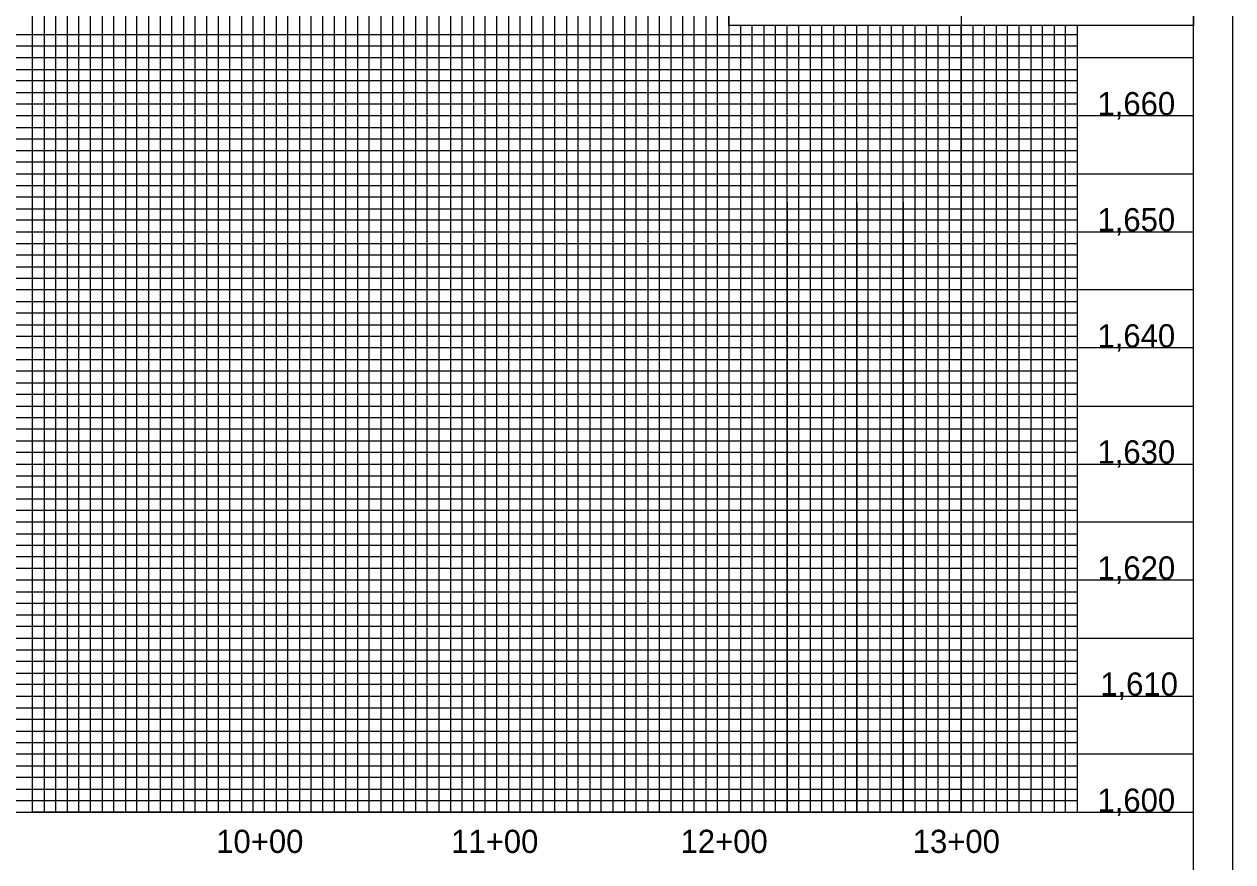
# Model space of a CAD drawing. Extents: x 505602 to 507286, y 483109 to 484209.
# Drawn here: x 506765 to 507286, y 483662 to 484023 of the extents above; entities that cross this region are included whole.
import ezdxf

# ---------------------------------------------------------------- set-up
doc = ezdxf.new("R2010")
doc.units = 0
for name, color, linetype in [('Exist Vertical Profile Vertical Axis Label', 7, 'Continuous'), ('Sheet Layout Profile Border Port 2', 7, 'Continuous'), ('Sheet Plot Border Outside CELL', 7, 'Continuous'), ('Sheet Profile CELL', 7, 'Continuous'), ('Sheet Profile Grid Major CELL', 7, 'Continuous'), ('Sheet Profile Grid Middle CELL', 7, 'Continuous'), ('Sheet Profile Grid Minor CELL', 7, 'Continuous'), ('Sheet Sticker Exception Certification CELL', 7, 'Continuous')]:
    doc.layers.add(name, color=color, linetype=linetype)

msp = doc.modelspace()

# ---------------------------------------------------------------- linework, layer by layer
at = {"layer": 'Sheet Layout Profile Border Port 2'}
msp.add_lwpolyline([(506769.08, 484183.71), (507169.08, 484183.71), (507169.08, 483683.71), (506769.08, 483683.71)], close=True, dxfattribs=at)
at = {"layer": 'Sheet Plot Border Outside CELL'}
msp.add_lwpolyline([(505602.08, 483108.71), (507286.08, 483108.71), (507286.08, 484208.71), (505602.08, 484208.71)], close=True, dxfattribs=at)
at = {"layer": 'Sheet Profile CELL'}
msp.add_line((505769.08, 483683.71), (507269.08, 483683.71), dxfattribs=at)
msp.add_lwpolyline([(507269.08, 484183.71), (505769.08, 484183.71), (505769.08, 483133.71), (507269.08, 483133.71)], close=True, dxfattribs=at)
at = {"layer": 'Sheet Profile Grid Major CELL'}
for points in [[(506719.08, 483683.71), (506769.08, 483683.71), (506769.08, 484183.71), (506819.08, 484183.71), (506819.08, 483683.71), (506869.08, 483683.71), (506869.08, 484183.71), (506919.08, 484183.71), (506919.08, 483683.71), (506969.08, 483683.71), (506969.08, 484183.71), (507019.08, 484183.71), (507019.08, 483683.71), (507069.08, 483683.71), (507069.08, 484183.71), (507095.38, 484183.71)], [(507219.08, 484022.66), (507219.08, 483683.71), (507269.08, 483683.71), (507269.08, 484033.71)], [(507119.08, 484022.66), (507119.08, 483683.71), (507169.08, 483683.71), (507169.08, 483683.71), (507169.08, 484022.66)], [(507269.08, 483983.71), (505769.08, 483983.71), (505769.08, 483933.71), (507269.08, 483933.71)], [(507269.08, 483883.71), (505769.08, 483883.71), (505769.08, 483833.71), (507269.08, 483833.71)], [(507269.08, 483783.71), (505769.08, 483783.71), (505769.08, 483783.71), (505769.08, 483733.71), (507269.08, 483733.71)]]:
    msp.add_lwpolyline(points, dxfattribs=at)
at = {"layer": 'Sheet Profile Grid Middle CELL'}
for points in [[(506744.08, 483683.71), (506794.08, 483683.71), (506794.08, 484183.71), (506844.08, 484183.71), (506844.08, 483683.71), (506894.08, 483683.71), (506894.08, 484183.71), (506944.08, 484183.71), (506944.08, 483683.71), (506994.08, 483683.71), (506994.08, 484183.71), (507044.08, 484183.71), (507044.08, 483683.71), (507094.08, 483683.71), (507094.08, 484022.66)], [(507094.08, 483946.51), (507094.08, 483683.71), (507144.08, 483683.71), (507144.08, 484022.66)], [(507144.08, 483946.51), (507144.08, 483683.71), (507194.08, 483683.71), (507194.08, 484022.66)], [(507269.08, 484008.71), (505769.08, 484008.71), (505769.08, 483958.71), (507094.08, 483958.71)], [(507094.08, 483958.71), (507269.08, 483958.71)], [(507269.08, 483908.71), (505769.08, 483908.71), (505769.08, 483858.71), (507269.08, 483858.71)], [(507269.08, 483808.71), (505769.08, 483808.71), (505769.08, 483758.71), (507269.08, 483758.71)], [(507269.08, 483708.71), (505769.08, 483708.71)]]:
    msp.add_lwpolyline(points, dxfattribs=at)
at = {"layer": 'Sheet Profile Grid Minor CELL'}
for p, q in [((505819.08, 484018.71), (507219.08, 484018.71)), ((507219.08, 483998.71), (505819.08, 483998.71)), ((505819.08, 483993.71), (507219.08, 483993.71)), ((507219.08, 483973.71), (505819.08, 483973.71)), ((505819.08, 483968.71), (507219.08, 483968.71)), ((507219.08, 483948.71), (505819.08, 483948.71)), ((505819.08, 483943.71), (507219.08, 483943.71)), ((507219.08, 483938.71), (505819.08, 483938.71)), ((505819.08, 483928.71), (507219.08, 483928.71)), ((507219.08, 483923.71), (505819.08, 483923.71)), ((505819.08, 483918.71), (507219.08, 483918.71)), ((507219.08, 483913.71), (505819.08, 483913.71)), ((505819.08, 483903.71), (507219.08, 483903.71)), ((507219.08, 483898.71), (505819.08, 483898.71)), ((505819.08, 483893.71), (507219.08, 483893.71)), ((507219.08, 483888.71), (505819.08, 483888.71)), ((505819.08, 483878.71), (507219.08, 483878.71)), ((507219.08, 483873.71), (505819.08, 483873.71)), ((505819.08, 483868.71), (507219.08, 483868.71)), ((507219.08, 483863.71), (505819.08, 483863.71)), ((505819.08, 483853.71), (507219.08, 483853.71)), ((507219.08, 483848.71), (505819.08, 483848.71)), ((505819.08, 483843.71), (507219.08, 483843.71)), ((507219.08, 483838.71), (505819.08, 483838.71)), ((505819.08, 483828.71), (507219.08, 483828.71)), ((507219.08, 483823.71), (505819.08, 483823.71)), ((505819.08, 483818.71), (507219.08, 483818.71)), ((507219.08, 483813.71), (505819.08, 483813.71)), ((505819.08, 483803.71), (507219.08, 483803.71)), ((507219.08, 483798.71), (505819.08, 483798.71)), ((507219.08, 483793.71), (505819.08, 483793.71)), ((507219.08, 483788.71), (505819.08, 483788.71)), ((505819.08, 483778.71), (507219.08, 483778.71)), ((507219.08, 483773.71), (505819.08, 483773.71)), ((505819.08, 483768.71), (507219.08, 483768.71)), ((507219.08, 483763.71), (505819.08, 483763.71)), ((505819.08, 483753.71), (507219.08, 483753.71)), ((507219.08, 483748.71), (505819.08, 483748.71)), ((505819.08, 483743.71), (507219.08, 483743.71)), ((507219.08, 483738.71), (505819.08, 483738.71)), ((505819.08, 483728.71), (507219.08, 483728.71)), ((507219.08, 483723.71), (505819.08, 483723.71)), ((505819.08, 483718.71), (507219.08, 483718.71)), ((507219.08, 483713.71), (505819.08, 483713.71)), ((505819.08, 483703.71), (507219.08, 483703.71)), ((507219.08, 483698.71), (505819.08, 483698.71)), ((505819.08, 483693.71), (507219.08, 483693.71))]:
    msp.add_line(p, q, dxfattribs=at)
for points in [[(506774.08, 484183.71), (506774.08, 483683.71), (506779.08, 483683.71), (506779.08, 484183.71)], [(506784.08, 484183.71), (506784.08, 483683.71), (506789.08, 483683.71), (506789.08, 484183.71)], [(506799.08, 484183.71), (506799.08, 483683.71), (506804.08, 483683.71), (506804.08, 484183.71)], [(506809.08, 484183.71), (506809.08, 483683.71), (506814.08, 483683.71), (506814.08, 484183.71)], [(506824.08, 484183.71), (506824.08, 483683.71), (506829.08, 483683.71), (506829.08, 484183.71)], [(506834.08, 484183.71), (506834.08, 483683.71), (506839.08, 483683.71), (506839.08, 484183.71)], [(506849.08, 484183.71), (506849.08, 483683.71), (506854.08, 483683.71), (506854.08, 484183.71)], [(506859.08, 484183.71), (506859.08, 483683.71), (506864.08, 483683.71), (506864.08, 484183.71)], [(506874.08, 484183.71), (506874.08, 483683.71), (506879.08, 483683.71), (506879.08, 484183.71)], [(506884.08, 484183.71), (506884.08, 483683.71), (506889.08, 483683.71), (506889.08, 484183.71)], [(506899.08, 484183.71), (506899.08, 483683.71), (506904.08, 483683.71), (506904.08, 484183.71)], [(506909.08, 484183.71), (506909.08, 483683.71), (506914.08, 483683.71), (506914.08, 484183.71)], [(506924.08, 484183.71), (506924.08, 483683.71), (506929.08, 483683.71), (506929.08, 484183.71)], [(506934.08, 484183.71), (506934.08, 483683.71), (506939.08, 483683.71), (506939.08, 484183.71)], [(506949.08, 484183.71), (506949.08, 483683.71), (506954.08, 483683.71), (506954.08, 484183.71)], [(506959.08, 484183.71), (506959.08, 483683.71)], [(506959.08, 483683.71), (506964.08, 483683.71), (506964.08, 484183.71)], [(506974.08, 484183.71), (506974.08, 483683.71), (506979.08, 483683.71), (506979.08, 484183.71)], [(506984.08, 484183.71), (506984.08, 483683.71), (506989.08, 483683.71), (506989.08, 484183.71)], [(506999.08, 484183.71), (506999.08, 483683.71), (507004.08, 483683.71), (507004.08, 484183.71)], [(507009.08, 484183.71), (507009.08, 483683.71), (507014.08, 483683.71), (507014.08, 484183.71)], [(507024.08, 484183.71), (507024.08, 483683.71), (507029.08, 483683.71), (507029.08, 484183.71)], [(507034.08, 484183.71), (507034.08, 483683.71), (507039.08, 483683.71), (507039.08, 484183.71)], [(507049.08, 484183.71), (507049.08, 483683.71), (507054.08, 483683.71), (507054.08, 484183.71)], [(507059.08, 484183.71), (507059.08, 483683.71), (507064.08, 483683.71), (507064.08, 484183.71)], [(507074.08, 484022.66), (507074.08, 483683.71), (507079.08, 483683.71), (507079.08, 484022.66)], [(507084.08, 484022.66), (507084.08, 483683.71), (507089.08, 483683.71), (507089.08, 484022.66)], [(507099.08, 484022.66), (507099.08, 483683.71), (507099.08, 483683.71), (507104.08, 483683.71), (507109.08, 483683.71), (507109.08, 484022.66)], [(507104.08, 484022.66), (507104.08, 483683.71)], [(507114.07, 484022.66), (507113.98, 483683.76), (507118.98, 483683.76), (507124.08, 483683.71), (507124.08, 484022.66)], [(507124.08, 483946.51), (507124.08, 483683.71), (507129.08, 483683.71), (507129.08, 484022.66)], [(507134.08, 484022.66), (507134.08, 483683.71), (507139.08, 483683.71), (507139.08, 484022.66)], [(507149.08, 484022.66), (507149.08, 483683.71), (507154.08, 483683.71), (507154.08, 484022.66)], [(507159.08, 484022.66), (507159.08, 483683.71), (507164.08, 483683.71), (507164.08, 484022.66)], [(507174.08, 484022.66), (507174.08, 483683.71), (507179.08, 483683.71), (507179.08, 484022.66)], [(507184.08, 484022.66), (507184.08, 483683.71), (507189.08, 483683.71), (507189.08, 484022.66)], [(507199.08, 484022.66), (507199.08, 483683.71), (507204.08, 483683.71), (507204.08, 484022.66)], [(507209.08, 484022.66), (507209.08, 483683.71), (507214.08, 483683.71), (507214.08, 484022.66)], [(507219.08, 484013.71), (505819.08, 484013.71), (505819.08, 484003.71), (507219.08, 484003.71)], [(507219.08, 483988.71), (505819.08, 483988.71), (505819.08, 483978.71), (507219.08, 483978.71)], [(507219.08, 483963.71), (505819.08, 483963.71), (505819.08, 483953.71), (507219.08, 483953.71)], [(507219.08, 483688.71), (505819.08, 483688.71)]]:
    msp.add_lwpolyline(points, dxfattribs=at)
at = {"layer": 'Sheet Sticker Exception Certification CELL'}
for p, q in [((507069.03, 484022.66), (507069.03, 484046.16)), ((507069.03, 484022.66), (507069.03, 484046.16)), ((507269.07, 484046.15), (507269.07, 484022.65)), ((507269.07, 484046.15), (507269.07, 484022.65)), ((507269.07, 484022.66), (507069.03, 484022.66)), ((507269.07, 484022.66), (507069.03, 484022.66))]:
    msp.add_line(p, q, dxfattribs=at)

# ---------------------------------------------------------------- texts
at = {"layer": 'Exist Vertical Profile Vertical Axis Label'}
for s, p in [('1,660', (507227.78, 483983.96)), ('1,650', (507227.78, 483933.96)), ('1,640', (507227.78, 483883.96)), ('1,630', (507227.78, 483833.96)), ('1,620', (507227.78, 483783.96)), ('1,610', (507228.97, 483733.96)), ('1,600', (507227.78, 483683.96)), ('10+00', (506848.21, 483666.21)), ('11+00', (506949.41, 483666.21)), ('12+00', (507048.21, 483666.21)), ('13+00', (507148.21, 483666.21))]:
    msp.add_text(s, height=10, dxfattribs=at).set_placement(p)

doc.saveas('drawing.dxf')
